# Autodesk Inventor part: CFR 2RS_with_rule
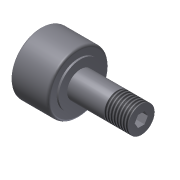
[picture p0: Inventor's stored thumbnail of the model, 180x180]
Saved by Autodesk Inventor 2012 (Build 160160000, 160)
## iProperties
Created: 2009-01
Part Number: CFR 2RS_with_rule
Material: Steel, Mild
Document SubType Name: Modeling
Mass: 458.851 g
Surface Area: 100.794 cm^2
Volume: 58.3779 cm^3
Density: 7.86 g/cm^3
Title: Cam Follower
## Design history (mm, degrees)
sketch "Sketch1"
  geometry: L1 (0, 0)-(-16.669, 0); L2 (-16.669, 0)-(-16.669, 12.7); L3 (-16.669, 12.7)-(-0.794, 12.7); L4 (-0.794, 12.7)-(-0.794, 0); L5 (0, 0)-(25.4, 0); L6 (25.4, 0)-(25.4, 5.556); L7 (25.4, 5.556)-(0, 5.556); L8 (0, 5.556)-(0, 0); L9 (0, 0)-(-0.794, 0); L10 (-0.794, 0)-(-0.794, 9.128); L11 (-0.794, 9.128)-(0, 9.128); L12 (0, 9.128)-(0, 0); L13 (-16.669, 0)-(-17.463, 0); L14 (-17.463, 0)-(-17.463, 9.128); L15 (-17.463, 9.128)-(-16.669, 9.128); L16 (-16.669, 9.128)-(-16.669, 0)
  constraints: 32 end point, 8 parallel, 4 horizontal, 4 perpendicular, 2 collinear, 2 point on line, 1 other
  dimensions: "RD" = 25.4 diameter of L3 L1; "WD" = 15.875 distance of L2.end L3.end; "SD" = 11.1125 diameter of L7 L1; "EL" = 0.79375 distance of L10.end L11.end; "SL" = 25.4 distance of L6.end L7.end
revolve "Revolution1" sketch "Sketch1" stored, may be unused: angle "d4" = 90 deg
fillet "Fillet1" dims "d19" = 1
sketch "Sketch5"
  geometry: L1 (-17.463, -9.128)-(-17.463, 9.128) reference; L2 (-20.463, 0)-(-17.463, 0); C1 r 6.846 at (-20.463, 0)
  constraints: 2 end point, 1 centre point, 1 coincident, 1 midpoint, 1 perpendicular
  dimensions: "d23" = 18.25625 distance of L1.start L1.end (derived); "d24" = 13.69219 diameter of C1 (= 0.75 x d23); "d25" = 3 distance from line of L1 C1.centre
extrude "Extrusion3" cut sketch "Sketch5" stored distance "d20" = 3; taper "d21" = 0 deg
hole "Hole2" diameter "HEX" = 4.7625; stored, may be unused: countersink angle "d46" = 90 deg, drill point angle "d48" = 118 deg; dims "d43" = 6, "d44" = 4, "d45" = 2, "d47" = 4.7625 (= HEX), "d49" = 10, "d50" = 10
sketch "Sketch6"
  geometry: L1 (-2.381, 1.375)-(0, 2.75); L2 (0, 2.75)-(2.381, 1.375); L3 (2.381, 1.375)-(2.381, -1.375); L4 (2.381, -1.375)-(0, -2.75); L5 (0, -2.75)-(-2.381, -1.375); L6 (-2.381, -1.375)-(-2.381, 1.375); C1 r 2.381 at (0, 0) reference; 1 further point
  constraints: 12 end point, 1 coincident, 1 tangent, 1 vertical, 13 other
extrude "Extrusion4" cut sketch "Sketch6" distance "d36" = 14; taper "d37" = 0 deg
feature "Metric Thread" dims "d52" = 0, "TL" = 10
feature "Inch Thread" dims "d53" = 10 (= TL), "d54" = 0
body "Solid1"
other parameters: "UnitMultiplier" = 25.4 [user parameter]
